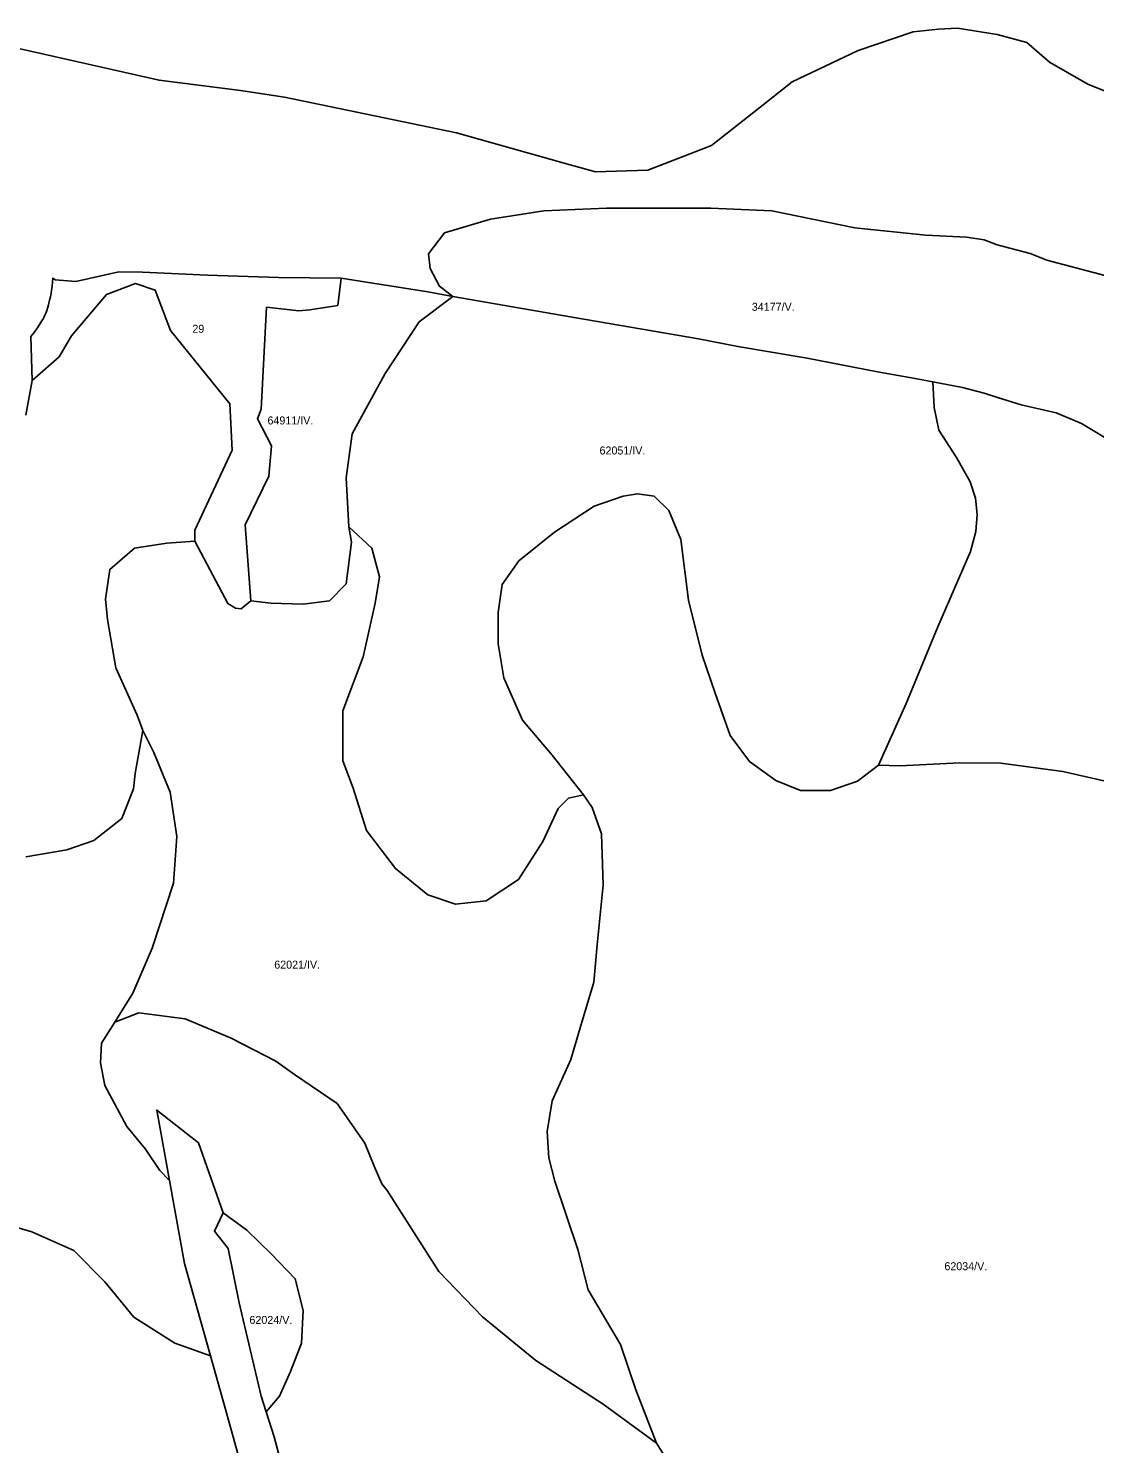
# Model space of a CAD drawing. Extents: x -521621 to -516761, y -1190184 to -1184927.
# Drawn here: x -519322 to -518790, y -1188092 to -1187385 of the extents above; entities that cross this region are included whole.
import ezdxf

# ---------------------------------------------------------------- set-up
doc = ezdxf.new("R2010")
doc.units = 0
doc.layers.add('BPEJ_s', color=7, linetype='Continuous')

msp = doc.modelspace()

# ---------------------------------------------------------------- linework, layer by layer
at = {"layer": 'BPEJ_s'}
for p, q in [((-518907.72, -1187396.04), (-518880.2, -1187386.72)), ((-518880.2, -1187386.72), (-518867.5, -1187385.44)), ((-518867.5, -1187385.44), (-518858.12, -1187384.95)), ((-518858.12, -1187384.95), (-518838.2, -1187388.01)), ((-518838.2, -1187388.01), (-518823.38, -1187392.1)), ((-519326.43, -1187395.19), (-519257, -1187410.86)), ((-518823.38, -1187392.1), (-518812.14, -1187401.82)), ((-518940.75, -1187411.71), (-518907.72, -1187396.04)), ((-518812.14, -1187401.82), (-518792.98, -1187412.81)), ((-519257, -1187410.86), (-519216.36, -1187415.95)), ((-519216.36, -1187415.95), (-519194.34, -1187419.33)), ((-518955.14, -1187423.15), (-518940.75, -1187411.71)), ((-518792.98, -1187412.81), (-518777.4, -1187419.2)), ((-519194.34, -1187419.33), (-519108.4, -1187437.13)), ((-518980.97, -1187443.48), (-518955.14, -1187423.15)), ((-519108.4, -1187437.13), (-519054.63, -1187452.38)), ((-519012.72, -1187455.77), (-518980.97, -1187443.48)), ((-519054.63, -1187452.38), (-519038.97, -1187456.61)), ((-519038.97, -1187456.61), (-519012.72, -1187455.77)), ((-519091.46, -1187480.34), (-519114.33, -1187487.11)), ((-519064.79, -1187476.1), (-519091.46, -1187480.34)), ((-519033.46, -1187474.83), (-519064.79, -1187476.1)), ((-518981.39, -1187474.83), (-519033.46, -1187474.83)), ((-518950.91, -1187476.1), (-518981.39, -1187474.83)), ((-518909.42, -1187484.57), (-518950.91, -1187476.1)), ((-519114.33, -1187487.11), (-519122.37, -1187497.71)), ((-518873.85, -1187488.39), (-518909.42, -1187484.57)), ((-518853.53, -1187489.23), (-518873.85, -1187488.39)), ((-518844.76, -1187490.58), (-518853.53, -1187489.23)), ((-518838.25, -1187493.19), (-518844.76, -1187490.58)), ((-518821.76, -1187497.54), (-518838.25, -1187493.19)), ((-519122.37, -1187497.71), (-519121.52, -1187504.91)), ((-518813.51, -1187500.79), (-518821.76, -1187497.54)), ((-518784.42, -1187508.4), (-518813.51, -1187500.79)), ((-519277.01, -1187506.71), (-519298.64, -1187511.54)), ((-519265.28, -1187506.76), (-519277.01, -1187506.71)), ((-519232.85, -1187508.38), (-519265.28, -1187506.76)), ((-519197.25, -1187509.54), (-519232.85, -1187508.38)), ((-519121.52, -1187504.91), (-519116.87, -1187513.8)), ((-519310.7, -1187515.97), (-519310.93, -1187517.36)), ((-519310.41, -1187513.76), (-519310.7, -1187515.97)), ((-519310.01, -1187509.72), (-519310.41, -1187513.76)), ((-519308.94, -1187510.56), (-519310.01, -1187509.72)), ((-519298.64, -1187511.54), (-519308.94, -1187510.56)), ((-519165.96, -1187509.87), (-519197.25, -1187509.54)), ((-519122.78, -1187516.59), (-519165.96, -1187509.87)), ((-519116.87, -1187513.8), (-519110.16, -1187518.97)), ((-519311.66, -1187520.8), (-519312.25, -1187523.11)), ((-519311.26, -1187519.05), (-519311.66, -1187520.8)), ((-519310.93, -1187517.36), (-519311.26, -1187519.05)), ((-519110.16, -1187518.97), (-519122.78, -1187516.59)), ((-519314.59, -1187529.47), (-519315.08, -1187530.38)), ((-519314.19, -1187528.68), (-519314.59, -1187529.47)), ((-519313.82, -1187527.87), (-519314.19, -1187528.68)), ((-519313.45, -1187526.94), (-519313.82, -1187527.87)), ((-519313.08, -1187525.9), (-519313.45, -1187526.94)), ((-519312.6, -1187524.31), (-519313.08, -1187525.9)), ((-519312.25, -1187523.11), (-519312.6, -1187524.31)), ((-519319.39, -1187536.9), (-519321.02, -1187538.88)), ((-519318.69, -1187535.99), (-519319.39, -1187536.9)), ((-519318.15, -1187535.24), (-519318.69, -1187535.99)), ((-519317.68, -1187534.57), (-519318.15, -1187535.24)), ((-519317.17, -1187533.79), (-519317.68, -1187534.57)), ((-519316.15, -1187532.17), (-519317.17, -1187533.79)), ((-519315.65, -1187531.35), (-519316.15, -1187532.17)), ((-519315.08, -1187530.38), (-519315.65, -1187531.35)), ((-519321.02, -1187538.88), (-519320.31, -1187560.93)), ((-519320.31, -1187560.93), (-519323.61, -1187578.33))]:
    msp.add_line(p, q, dxfattribs=at)
for points in [[(-518777.4, -1187419.2), (-518792.98, -1187412.81), (-518812.14, -1187401.82), (-518823.38, -1187392.1), (-518838.2, -1187388.01), (-518858.12, -1187384.95), (-518867.5, -1187385.44), (-518880.2, -1187386.72), (-518907.72, -1187396.04), (-518940.75, -1187411.71), (-518955.14, -1187423.15), (-518980.97, -1187443.48), (-519012.72, -1187455.77), (-519038.97, -1187456.61), (-519054.63, -1187452.38), (-519108.4, -1187437.13), (-519194.34, -1187419.33), (-519216.36, -1187415.95), (-519257, -1187410.86), (-519326.43, -1187395.19)], [(-518778.94, -1187592.67), (-518796.09, -1187582.5), (-518808.72, -1187577.04), (-518826.24, -1187573.01), (-518838.03, -1187569.42), (-518844.76, -1187567.25), (-518855.62, -1187564.43), (-518870.38, -1187561.6), (-518879.27, -1187559.87), (-518897.99, -1187556.59), (-518933.12, -1187549.81), (-518967.84, -1187543.88), (-518987.43, -1187540.18), (-519055.51, -1187528.45), (-519110.16, -1187518.97), (-519116.87, -1187513.8), (-519121.52, -1187504.91), (-519122.37, -1187497.71), (-519114.33, -1187487.11), (-519091.46, -1187480.34), (-519064.79, -1187476.1), (-519033.46, -1187474.83), (-518981.39, -1187474.83), (-518950.91, -1187476.1), (-518909.42, -1187484.57), (-518873.85, -1187488.39), (-518853.53, -1187489.23), (-518844.76, -1187490.58), (-518838.25, -1187493.19), (-518821.76, -1187497.54), (-518813.51, -1187500.79), (-518784.42, -1187508.4)], [(-519323.61, -1187578.33), (-519320.31, -1187560.93), (-519306.91, -1187549.18), (-519300.78, -1187538.69), (-519283.32, -1187517.95), (-519268.8, -1187512.49), (-519258.98, -1187515.74), (-519251.29, -1187535.93), (-519221.71, -1187572.62), (-519220.42, -1187595.79), (-519239.07, -1187635.7), (-519239.07, -1187641.18), (-519253.19, -1187642.16), (-519269.28, -1187644.7), (-519281.56, -1187655.29), (-519283.67, -1187670.12), (-519282.83, -1187680.29), (-519278.59, -1187704.44), (-519268.01, -1187728.16), (-519265.04, -1187735.78), (-519268.85, -1187757.39), (-519269.7, -1187765.01), (-519275.63, -1187779.84), (-519289.6, -1187790.85), (-519303.15, -1187795.52), (-519323.47, -1187798.9)], [(-518763.58, -1187765.87), (-518805.39, -1187756.37), (-518836.52, -1187752.22), (-518856.98, -1187751.92), (-518886.93, -1187753.41), (-518897.6, -1187753.11), (-518883.67, -1187722.25), (-518867.95, -1187683.98), (-518851.64, -1187646.3), (-518848.89, -1187636.32), (-518848.24, -1187627.84), (-518849.1, -1187619.81), (-518851.71, -1187611.56), (-518858.65, -1187599.39), (-518867.34, -1187585.71), (-518869.72, -1187574.42), (-518870.38, -1187561.6), (-518855.62, -1187564.43), (-518844.76, -1187567.25), (-518838.03, -1187569.42), (-518826.24, -1187573.01), (-518808.72, -1187577.04), (-518796.09, -1187582.5), (-518778.94, -1187592.67)], [(-518997.05, -1188110.14), (-519008.55, -1188091.89), (-519018.86, -1188065.31), (-519026.39, -1188042.7), (-519042.64, -1188015.33), (-519047.8, -1187995.09), (-519059.3, -1187960.98), (-519062.25, -1187949.29), (-519063.1, -1187936.16), (-519060.56, -1187920.91), (-519054.21, -1187906.93), (-519051.24, -1187900.15), (-519046.59, -1187884.48), (-519039.81, -1187861.6), (-519038.12, -1187842.96), (-519035.16, -1187812.88), (-519036, -1187787.47), (-519040.66, -1187774.33), (-519044.89, -1187767.98), (-519060.56, -1187748.07), (-519075.38, -1187730.7), (-519084.69, -1187709.52), (-519087.65, -1187692.57), (-519087.65, -1187676.9), (-519085.54, -1187662.92), (-519077.29, -1187651.05), (-519059.5, -1187636.8), (-519039.64, -1187623.75), (-519025.11, -1187618.71), (-519017.99, -1187617.52), (-519009.69, -1187618.71), (-519002.28, -1187625.83), (-518996.34, -1187640.36), (-518992.49, -1187670.63), (-518985.67, -1187698.22), (-518979.15, -1187717.21), (-518971.73, -1187738.28), (-518961.95, -1187751.33), (-518948.9, -1187760.82), (-518936.45, -1187765.87), (-518921.62, -1187765.87), (-518907.98, -1187761.12), (-518897.6, -1187753.11), (-518886.93, -1187753.41), (-518856.98, -1187751.92), (-518836.52, -1187752.22), (-518805.39, -1187756.37), (-518763.58, -1187765.87)], [(-519323.47, -1187798.9), (-519303.15, -1187795.52), (-519289.6, -1187790.85), (-519275.63, -1187779.84), (-519269.7, -1187765.01), (-519268.85, -1187757.39), (-519265.04, -1187735.78), (-519259.54, -1187746.8), (-519251.5, -1187766.71), (-519248.11, -1187788.74), (-519249.8, -1187812.04), (-519260.39, -1187844.66), (-519270.12, -1187867.11), (-519279.02, -1187881.51), (-519285.79, -1187892.1), (-519286.21, -1187901.84), (-519284.1, -1187913.28), (-519273.09, -1187933.62), (-519263.77, -1187945.06), (-519256.58, -1187955.65), (-519251.75, -1187960.69), (-519244.2, -1188002.13), (-519231.21, -1188048.3), (-519249.12, -1188042.03), (-519269.53, -1188028.9), (-519284.11, -1188011.39), (-519299.56, -1187995.64), (-519320.55, -1187986.31), (-519334.84, -1187982.22)], [(-519184.34, -1188145.83), (-519199.49, -1188088.69), (-519203.45, -1188076.36), (-519196.87, -1188068.49), (-519191.32, -1188056.19), (-519185.77, -1188041.91), (-519184.98, -1188025.64), (-519188.94, -1188009.77), (-519200.84, -1187997.48), (-519213.13, -1187985.57), (-519225, -1187976.8), (-519237.22, -1187941.87), (-519258.16, -1187925.51), (-519251.75, -1187960.69), (-519256.58, -1187955.65), (-519263.77, -1187945.06), (-519273.09, -1187933.62), (-519284.1, -1187913.28), (-519286.21, -1187901.84), (-519285.79, -1187892.1), (-519279.02, -1187881.51), (-519267.16, -1187876.85), (-519243.88, -1187879.82), (-519221.01, -1187889.56), (-519198.58, -1187901), (-519189.26, -1187907.78), (-519168.09, -1187922.18), (-519154.12, -1187942.09), (-519149.47, -1187953.53), (-519145.66, -1187962.42), (-519142.95, -1187965.74), (-519117.18, -1188006.2), (-519095.38, -1188028.82), (-519068.81, -1188050.64), (-519035.11, -1188072.46), (-519008.55, -1188091.89), (-518997.05, -1188110.14)], [(-519213.76, -1188110.85), (-519224.72, -1188071.37), (-519231.21, -1188048.3), (-519244.2, -1188002.13), (-519251.75, -1187960.69), (-519258.16, -1187925.51), (-519237.22, -1187941.87), (-519225, -1187976.8), (-519229.37, -1187985.97), (-519222.39, -1187994.71), (-519217, -1188021.74), (-519205.97, -1188068.51), (-519203.45, -1188076.36), (-519199.49, -1188088.69), (-519184.34, -1188145.83)], [(-519334.84, -1187982.22), (-519320.55, -1187986.31), (-519299.56, -1187995.64), (-519284.11, -1188011.39), (-519269.53, -1188028.9), (-519249.12, -1188042.03), (-519231.21, -1188048.3), (-519224.72, -1188071.37), (-519213.76, -1188110.85)]]:
    msp.add_lwpolyline(points, dxfattribs=at)
for points in [[(-519320.31, -1187560.93), (-519321.02, -1187538.88), (-519319.39, -1187536.9), (-519318.69, -1187535.99), (-519318.15, -1187535.24), (-519317.68, -1187534.57), (-519317.17, -1187533.79), (-519316.15, -1187532.17), (-519315.65, -1187531.35), (-519315.08, -1187530.38), (-519314.59, -1187529.47), (-519314.19, -1187528.68), (-519313.82, -1187527.87), (-519313.45, -1187526.94), (-519313.08, -1187525.9), (-519312.6, -1187524.31), (-519312.25, -1187523.11), (-519311.66, -1187520.8), (-519311.26, -1187519.05), (-519310.93, -1187517.36), (-519310.7, -1187515.97), (-519310.41, -1187513.76), (-519310.01, -1187509.72), (-519308.94, -1187510.56), (-519298.64, -1187511.54), (-519277.01, -1187506.71), (-519265.28, -1187506.76), (-519232.85, -1187508.38), (-519197.25, -1187509.54), (-519165.96, -1187509.87), (-519167.64, -1187523.44), (-519181.66, -1187525.7), (-519187.08, -1187526.15), (-519203.36, -1187524.34), (-519205.95, -1187575.2), (-519207.88, -1187580.02), (-519200.81, -1187593.54), (-519202.09, -1187608.67), (-519213.99, -1187633.13), (-519211.1, -1187671.11), (-519215.92, -1187674.97), (-519218.81, -1187674.65), (-519222.67, -1187672.4), (-519239.07, -1187641.18), (-519239.07, -1187635.7), (-519220.42, -1187595.79), (-519221.71, -1187572.62), (-519251.29, -1187535.93), (-519258.98, -1187515.74), (-519268.8, -1187512.49), (-519283.32, -1187517.95), (-519300.78, -1187538.69), (-519306.91, -1187549.18)], [(-519211.1, -1187671.11), (-519213.99, -1187633.13), (-519202.09, -1187608.67), (-519200.81, -1187593.54), (-519207.88, -1187580.02), (-519205.95, -1187575.2), (-519203.36, -1187524.34), (-519187.08, -1187526.15), (-519181.66, -1187525.7), (-519167.64, -1187523.44), (-519165.96, -1187509.87), (-519122.78, -1187516.59), (-519110.16, -1187518.97), (-519127.03, -1187531.59), (-519143.96, -1187557.44), (-519149.89, -1187568.03), (-519160.47, -1187587.51), (-519163.44, -1187609.54), (-519162.17, -1187634.11), (-519160.9, -1187641.74), (-519163.44, -1187662.5), (-519171.9, -1187670.97), (-519185.03, -1187672.66), (-519201.12, -1187672.24)], [(-519162.17, -1187634.11), (-519163.44, -1187609.54), (-519160.47, -1187587.51), (-519149.89, -1187568.03), (-519143.96, -1187557.44), (-519127.03, -1187531.59), (-519110.16, -1187518.97), (-519055.51, -1187528.45), (-518987.43, -1187540.18), (-518967.84, -1187543.88), (-518933.12, -1187549.81), (-518897.99, -1187556.59), (-518879.27, -1187559.87), (-518870.38, -1187561.6), (-518869.72, -1187574.42), (-518867.34, -1187585.71), (-518858.65, -1187599.39), (-518851.71, -1187611.56), (-518849.1, -1187619.81), (-518848.24, -1187627.84), (-518848.89, -1187636.32), (-518851.64, -1187646.3), (-518867.95, -1187683.98), (-518883.67, -1187722.25), (-518897.6, -1187753.11), (-518907.98, -1187761.12), (-518921.62, -1187765.87), (-518936.45, -1187765.87), (-518948.9, -1187760.82), (-518961.95, -1187751.33), (-518971.73, -1187738.28), (-518979.15, -1187717.21), (-518985.67, -1187698.22), (-518992.49, -1187670.63), (-518996.34, -1187640.36), (-519002.28, -1187625.83), (-519009.69, -1187618.71), (-519017.99, -1187617.52), (-519025.11, -1187618.71), (-519039.64, -1187623.75), (-519059.5, -1187636.8), (-519077.29, -1187651.05), (-519085.54, -1187662.92), (-519087.65, -1187676.9), (-519087.65, -1187692.57), (-519084.69, -1187709.52), (-519075.38, -1187730.7), (-519060.56, -1187748.07), (-519044.89, -1187767.98), (-519052.51, -1187769.67), (-519057.6, -1187774.76), (-519065.22, -1187791.28), (-519077.49, -1187810.34), (-519093.58, -1187820.93), (-519108.82, -1187822.63), (-519122.79, -1187817.97), (-519138.88, -1187804.83), (-519153.28, -1187785.77), (-519160.05, -1187764.59), (-519165.13, -1187751.03), (-519165.13, -1187726.04), (-519154.97, -1187698.93), (-519149.04, -1187672.24), (-519146.93, -1187659.11), (-519150.74, -1187644.7)], [(-519279.02, -1187881.51), (-519270.12, -1187867.11), (-519260.39, -1187844.66), (-519249.8, -1187812.04), (-519248.11, -1187788.74), (-519251.5, -1187766.71), (-519259.54, -1187746.8), (-519265.04, -1187735.78), (-519268.01, -1187728.16), (-519278.59, -1187704.44), (-519282.83, -1187680.29), (-519283.67, -1187670.12), (-519281.56, -1187655.29), (-519269.28, -1187644.7), (-519253.19, -1187642.16), (-519239.07, -1187641.18), (-519222.67, -1187672.4), (-519218.81, -1187674.65), (-519215.92, -1187674.97), (-519211.1, -1187671.11), (-519201.12, -1187672.24), (-519185.03, -1187672.66), (-519171.9, -1187670.97), (-519163.44, -1187662.5), (-519160.9, -1187641.74), (-519162.17, -1187634.11), (-519150.74, -1187644.7), (-519146.93, -1187659.11), (-519149.04, -1187672.24), (-519154.97, -1187698.93), (-519165.13, -1187726.04), (-519165.13, -1187751.03), (-519160.05, -1187764.59), (-519153.28, -1187785.77), (-519138.88, -1187804.83), (-519122.79, -1187817.97), (-519108.82, -1187822.63), (-519093.58, -1187820.93), (-519077.49, -1187810.34), (-519065.22, -1187791.28), (-519057.6, -1187774.76), (-519052.51, -1187769.67), (-519044.89, -1187767.98), (-519040.66, -1187774.33), (-519036, -1187787.47), (-519035.16, -1187812.88), (-519038.12, -1187842.96), (-519039.81, -1187861.6), (-519046.59, -1187884.48), (-519051.24, -1187900.15), (-519054.21, -1187906.93), (-519060.56, -1187920.91), (-519063.1, -1187936.16), (-519062.25, -1187949.29), (-519059.3, -1187960.98), (-519047.8, -1187995.09), (-519042.64, -1188015.33), (-519026.39, -1188042.7), (-519018.86, -1188065.31), (-519008.55, -1188091.89), (-519035.11, -1188072.46), (-519068.81, -1188050.64), (-519095.38, -1188028.82), (-519117.18, -1188006.2), (-519142.95, -1187965.74), (-519145.66, -1187962.42), (-519149.47, -1187953.53), (-519154.12, -1187942.09), (-519168.09, -1187922.18), (-519189.26, -1187907.78), (-519198.58, -1187901), (-519221.01, -1187889.56), (-519243.88, -1187879.82), (-519267.16, -1187876.85)], [(-519225, -1187976.8), (-519213.13, -1187985.57), (-519200.84, -1187997.48), (-519188.94, -1188009.77), (-519184.98, -1188025.64), (-519185.77, -1188041.91), (-519191.32, -1188056.19), (-519196.87, -1188068.49), (-519203.45, -1188076.36), (-519205.97, -1188068.51), (-519217, -1188021.74), (-519222.39, -1187994.71), (-519229.37, -1187985.97)]]:
    msp.add_lwpolyline(points, close=True, dxfattribs=at)

# ---------------------------------------------------------------- texts
for s, p in [('34177/V.', (-518960.86, -1187526.11)), ('29', (-519240.36, -1187537.09)), ('64911/IV.', (-519202.82, -1187582.89)), ('62051/IV.', (-519036.92, -1187597.9)), ('62021/IV.', (-519199.44, -1187854.82)), ('62034/V.', (-518864.64, -1188005.52)), ('62024/V.', (-519211.83, -1188032.36))]:
    msp.add_text(s, height=4, dxfattribs=at).set_placement(p)

doc.saveas('drawing.dxf')
